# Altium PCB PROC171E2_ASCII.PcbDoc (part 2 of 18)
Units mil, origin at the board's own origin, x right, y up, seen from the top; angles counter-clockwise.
Board outline 7700 x 2300 mil, 6 copper layers (Top Layer, GND 1, SIG 1, SIG 2, GND 2, Bottom Layer), stack 61.062 mil thick; 938 components, 688 nets, 11933 pads, 1723 vias.
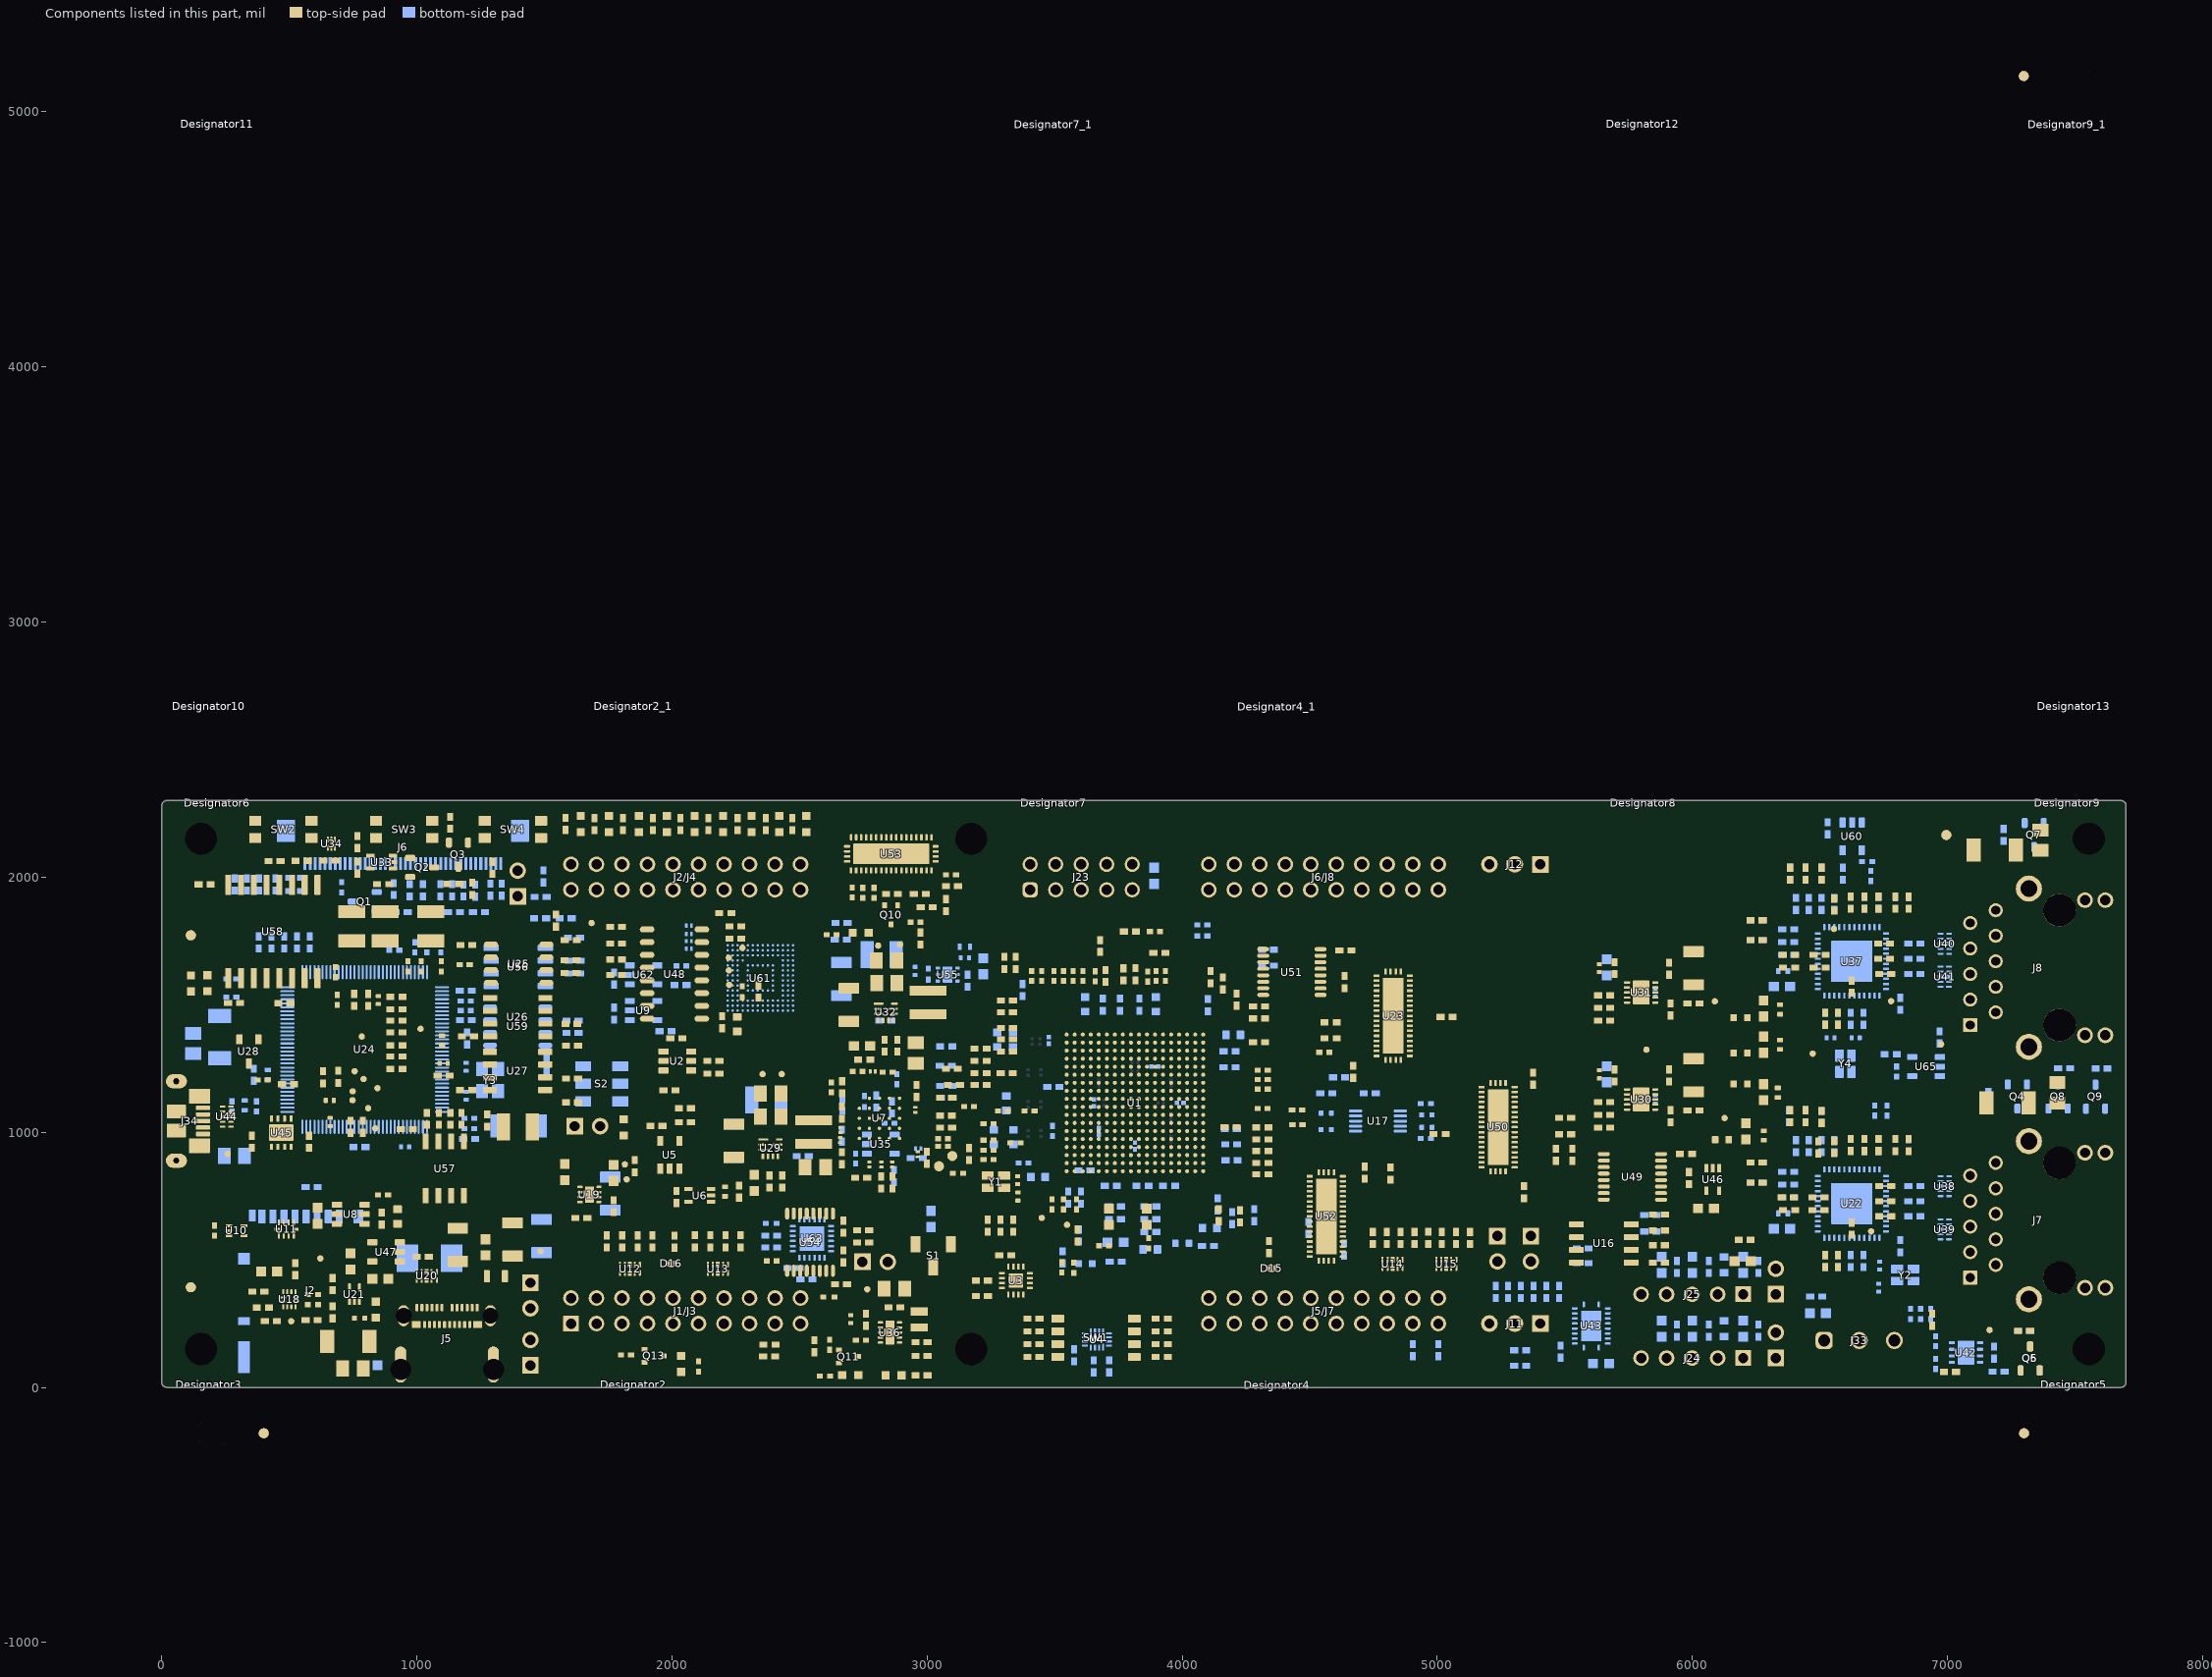
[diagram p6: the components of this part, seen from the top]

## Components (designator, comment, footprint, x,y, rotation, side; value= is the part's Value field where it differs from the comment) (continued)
C108 "GRM188R72A104KA35D" 0603 1771.58,840.73 r90 top
C109 "GRM1555C1H102JA01D" 0402 1771.58,710 r270 top
C110 "GRM188R72A104KA35D" 0603 740,493.54 r90 top
C111 "GRM155R71E104KE14D" 0402 5009,992.82 r0 top
C112 "GJM1555C1H120JB01D" FP-GJM1555C1H120JB01D_0402-MFG 6730.7,390.77 r270 bottom
C113 "GJM1555C1H120JB01D" FP-GJM1555C1H120JB01D_0402-MFG 6733.44,477.16 r270 bottom
C114 "GRM188Z71A106MA73D" 0603 6279,1343.28 r90 top
C115 "GRM1555C1E103JE01D" FP-GRM1555C1E103JE01D_0402-MFG 6344,1343.46 r270 top
C116 "GRM155R70J105MA12D" 0402 6556.28,941.71 r90 top
C117 "GRM155R71E104KE14D" 0402 6556.28,945.08 r90 bottom
C118 "GRM155R70J105MA12D" 0402 6493.94,745.04 r0 top
C119 "GRM155R71E104KE14D" 0402 6374.14,745.04 r180 top
C120 "GRM155R70J105MA12D" 0402 6755.41,729.88 r180 top
C121 "GRM155R71E104KE14D" 0402 6870.21,729.88 r0 bottom
C122 "GRM188Z71A106MA73D" 0603 6210,1003.65 r90 top
C123 "GRM1555C1E103JE01D" FP-GRM1555C1E103JE01D_0402-MFG 6280.09,987.15 r270 top
C124 "GRM155R70J105MA12D" 0402 6755.41,670.83 r180 top
C125 "GRM155R71E104KE14D" 0402 6870.21,670.83 r0 bottom
C126 "GRM155R70J105MA12D" 0402 6755.41,788.94 r180 top
C127 "GRM155R71E104KE14D" 0402 6870.21,788.94 r0 bottom
C128 "GRM188Z71A106MA73D" 0603 6351.36,621.24 r180 bottom
C129 "GRM1555C1E103JE01D" FP-GRM1555C1E103JE01D_0402-MFG 6355.51,681.97 r0 bottom
C130 "GRM155R70J105MA12D" 0402 6625,622.13 r90 top
C131 "GRM155R71E104KE14D" 0402 6670,495 r270 bottom
C132 "GRM155R70J105MA12D" 0402 6493.94,695.04 r0 top
C133 "GRM155R71E104KE14D" 0402 6379.14,695.04 r180 top
C134 "GRM155R71E104KE14D" 0402 1205.5,974.22 r180 bottom
C135 "GRM1555C1E103JE01D" FP-GRM1555C1E103JE01D_0402-MFG 325,1105.38 r90 bottom
C136 "GRM155R71E104KE14D" 0402 1607.87,1117.23 r180 top
C137 "GRM155R71E104KE14D" 0402 1607.87,1340 r180 top
C138 "GRM155R71E104KE14D" 0402 1603.77,1753.19 r180 top
C139 "GRM155R71E104KE14D" 0402 1193.04,1165.27 r0 top
C140 "GRM155R71E104KE14D" 0402 1200.59,1376.28 r0 top
C141 "GRM155R71E104KE14D" 0402 1194.14,1733.64 r0 top
C142 "GRM155R71E104KE14D" 0402 1191.36,1554.93 r0 bottom
C143 "GJM1555C1H8R0DB01D" FP-GJM1555C1H8R0DB01D_0402-MFG 1193.21,1143.27 r270 bottom
C144 "GJM1555C1H8R0DB01D" FP-GJM1555C1H8R0DB01D_0402-MFG 1193.07,1256.29 r90 bottom
C145 "GRM155R71E104KE14D" 0402 495.31,1188.47 r0 top
C146 "GRM155C71A105KE11D" FP-GRM155C71A105KE11D_0402-MFG 954.01,942.22 r180 bottom
C147 "GRM155R71E104KE14D" 0402 787.63,1021.22 r90 top
C148 "GRM155C71A105KE11D" FP-GRM155C71A105KE11D_0402-MFG 848.81,1517.94 r270 top
C149 "GRM1555C1E103JE01D" FP-GRM1555C1E103JE01D_0402-MFG 1098.65,1359.8 r90 top
C150 "GRM155R71E104KE14D" 0402 480.5,1505.66 r0 top
C151 "GRM155R71E104KE14D" 0402 360.82,1225.67 r270 bottom
C152 "GRM1555C1E103JE01D" FP-GRM1555C1E103JE01D_0402-MFG 415.82,1225.67 r90 bottom
C153 "GRM155C81C225KE11D" 0402 1105,1221.57 r180 top
C154 "GRM155R71E104KE14D" 0402 774.98,941.85 r180 bottom
C155 "GRM155R71E104KE14D" 0402 740.38,1021.22 r270 top
C156 "GRM155C71A105KE11D" FP-GRM155C71A105KE11D_0402-MFG 1105,1270 r180 top
C157 "GRM21BZ71A226ME15L" 0805_HV 2387.33,1061.68 r180 top
C158 "GRM21BZ71A226ME15L" 0805_HV 2387.33,1151.68 r180 top
C159 "GRM32ER71A476ME15L" 1210_270 2370.42,1126.68 r180 bottom
C160 "GRM188R71E474KA12D" 0603 2322.84,801.68 r270 top
C161 "GRM188Z71C475KE21D" 0603 5664.06,1227.1 r90 bottom
C162 "GRM155C71A105KE11D" FP-GRM155C71A105KE11D_0402-MFG 5635.58,1227.04 r270 top
C163 "GRM155R71E104KE14D" 0402 5695.21,1222.1 r90 top
C164 "GRM32EC72A106KE05L" FP-GRM32EC72A106KE05L_1210-MFG 6004.13,1223.43 r270 top
C165 "GRM155R71E104KE14D" 0402 5909.13,1222.1 r90 top
C166 "GCM155R72A272KA37D" FP-GCM155R72A272KA37D_0402-MFG 5854.25,1128.43 r270 bottom
C167 "GRM32EC72A106KE05L" FP-GRM32EC72A106KE05L_1210-MFG 2242.33,966.68 r270 top
C168 "GRM32EC72A106KE05L" FP-GRM32EC72A106KE05L_1210-MFG 2242.33,966.68 r270 bottom
C169 "GRM21BZ71A226ME15L" 0805_HV 2842.02,1584.28 r180 top
C170 "GRM21BZ71A226ME15L" 0805_HV 2841.41,1673.07 r180 top
C171 "GRM32ER71A476ME15L" 1210_270 2821.87,1696.91 r180 bottom
C172 "GRM188Z71C475KE21D" 0603 5664.13,1646.29 r90 bottom
C173 "GRM155C71A105KE11D" FP-GRM155C71A105KE11D_0402-MFG 5635.58,1643.07 r270 top
C174 "GRM155R71E104KE14D" 0402 5695.21,1643.29 r90 top
C175 "GRM32EC72A106KE05L" FP-GRM32EC72A106KE05L_1210-MFG 6004.13,1642.62 r270 top
C176 "GRM155R71E104KE14D" 0402 5909.13,1641.29 r90 top
C177 "GRM188R71E474KA12D" 0603 2745.09,1338.05 r180 top
C178 "GCM155R72A272KA37D" FP-GCM155R72A272KA37D_0402-MFG 5854.25,1547.62 r270 bottom
C179 "GRM32EC72A106KE05L" FP-GRM32EC72A106KE05L_1210-MFG 2663.88,1600.34 r270 bottom
C180 "GRM32EC72A106KE05L" FP-GRM32EC72A106KE05L_1210-MFG 2694,1499.3 r270 top
C181 "GRM155R71E104KE14D" 0402 657.31,2065 r180 top
C182 "GRM155R71E104KE14D" 0402 766.92,2037.31 r90 top
C183 "GRM155R71E104KE14D" 0402 522.55,1944.88 r0 bottom
C184 "GRM155R71E104KE14D" 0402 522.55,1997.05 r0 bottom
C185 "GRM21BZ71A226ME15L" 0805_HV 2872,387 r180 top
C186 "GRM155R71E104KE14D" 0402 2872,314 r180 top
C187 "GRM155C71A105KE11D" FP-GRM155C71A105KE11D_0402-MFG 2700.34,267.42 r270 top
C188 "GRM155R71E104KE14D" 0402 2760.42,264.96 r90 top
C189 "GJM1555C1H120JB01D" FP-GJM1555C1H120JB01D_0402-MFG 6541.38,1370 r0 bottom
C190 "GJM1555C1H120JB01D" FP-GJM1555C1H120JB01D_0402-MFG 6640.35,1370.13 r180 bottom
C191 "GRM188Z71A106MA73D" 0603 6279,1485.21 r90 top
C192 "GRM1555C1E103JE01D" FP-GRM1555C1E103JE01D_0402-MFG 6344,1481.27 r270 top
C193 "GRM155R70J105MA12D" 0402 6556.28,1891.71 r90 top
C194 "GRM155R71E104KE14D" 0402 6556.28,1895.08 r90 bottom
C195 "GRM155R70J105MA12D" 0402 6498.94,1695.04 r0 top
C196 "GRM155R71E104KE14D" 0402 6379.14,1695.04 r180 top
C197 "GRM155R70J105MA12D" 0402 6751.41,1679.88 r180 top
C198 "GRM155R71E104KE14D" 0402 6870.21,1679.88 r0 bottom
C199 "GRM188Z71A106MA73D" 0603 6278.93,1156.97 r270 top
C200 "GRM1555C1E103JE01D" FP-GRM1555C1E103JE01D_0402-MFG 6334.77,1155 r90 top
C201 "GRM155R70J105MA12D" 0402 6755.41,1620.83 r180 top
C202 "GRM155R71E104KE14D" 0402 6870.21,1620.83 r0 bottom
C203 "GRM155R70J105MA12D" 0402 6751.41,1738.94 r180 top
C204 "GRM155R71E104KE14D" 0402 6870.21,1738.94 r0 bottom
C205 "GRM188Z71A106MA73D" 0603 6351.36,1571.24 r180 bottom
C206 "GRM1555C1E103JE01D" FP-GRM1555C1E103JE01D_0402-MFG 6355.51,1631.97 r0 bottom
C207 "GRM155R70J105MA12D" 0402 6625,1570.47 r90 top
C208 "GRM155R71E104KE14D" 0402 6670,1445 r270 bottom
C209 "GRM155R70J105MA12D" 0402 6498.94,1645.04 r0 top
C210 "GRM155R71E104KE14D" 0402 6379.14,1645.04 r180 top
C211 "GRM188R72A104KA35D" 0603 5880,230 r90 bottom
C212 "GRM188R72A104KA35D" 0603 5880,480 r90 bottom
C213 "GRM188R72A104KA35D" 0603 3890,2005 r270 bottom
C214 "GRM1885C1H102JA01D" 0603 6199.18,230 r90 bottom
C215 "GQM1875C2E101JB12D" FP-GQM1875C2E101JB12D_0603-MFG 6124.18,230 r270 bottom
C216 "GRM1885C1H102JA01D" 0603 6000,230 r90 bottom
C217 "GRM1885C1H102JA01D" 0603 6199.18,480 r90 bottom
C218 "GQM1875C2E101JB12D" FP-GQM1875C2E101JB12D_0603-MFG 6124.18,480 r270 bottom
C219 "GRM1885C1H102JA01D" 0603 6000,480 r90 bottom
C220 "GRM1885C1H102JA01D" 0603 6492.17,290.82 r0 bottom
C221 "GRM1885C1H102JA01D" 0603 6197.13,494.67 r180 top
C222 "GRM155R71H472KA01D" 0402 6940,265 r90 top
C223 "GRM155R71E104KE14D" 0402 5483.66,140.04 r90 bottom
C224 "GRM188R72A104KA35D" 0603 5642.05,93.47 r180 bottom
C225 "GRM155R71E104KE14D" 0402 7182.8,136.46 r270 bottom
C226 "GRM155R71E104KE14D" 0402 7010,60.4 r180 top
C227 "GRM21BZ71E106KE15L" 0805_HV 285,906.68 r0 bottom
C228 "GJM1555C1H150FB01D" FP-GJM1555C1H150FB01D_0402-MFG 658.65,1124.76 r0 top
C229 "GR442QR73D102KW01L" 1808 731.46,180.12 r0 top
C230 "GR442QR73D102KW01L" 1808 227.89,1373.06 r270 bottom
C231 "GRM155C81C225KE11D" 0402 352.83,962.27 r90 top
C232 "GRM155C71A105KE11D" FP-GRM155C71A105KE11D_0402-MFG 660,1040.15 r270 top
C233 "GRM155R71E104KE14D" 0402 577.56,962.27 r270 top
C234 "GR442QR73D102KW01L" 1808 1398.86,1025 r0 bottom
C235 "GR442QR73D102KW01L" 1808 7235,1115 r0 top
C236 "CL10A335KP8NNNC" FP-CL10A335KP8NNNC_0603-MFG 2255.95,1423.5 r270 top
C237 "GRM155R71E104KE14D" 0402 2195.94,1431.38 r270 top
C238 "GRM155R71E104KE14D" 0402 5376.11,1209.78 r270 top
C239 "GRM155R71E104KE14D" 0402 5339.88,764.77 r90 top
C240 "GRM155R71E104KE14D" 0402 4670.38,1236.85 r90 top
C241 "GRM155R71E104KE14D" 0402 4636.65,1588.39 r90 top
C242 "GRM155R71E104KE14D" 0402 5036.38,1451.95 r180 top
C243 "GRM155R71E104KE14D" 0402 4495.23,625.31 r90 bottom
C244 "GRM155R71E104KE14D" 0402 4635,540.45 r270 bottom
C245 "GRM155R71E104KE14D" 0402 4715,841.18 r270 top
C246 "GRM155R71E104KE14D" 0402 4640,1712.48 r180 top
C247 "GR442QR73D102KW01L" 1808 7185.15,2106.97 r0 top
C248 "GRM188R72A104KA35D" 0603 6053.19,701.15 r180 top
C249 "GRM188R72A104KA35D" 0603 856.86,425.41 r0 top
C250 "GRM155R71E104KE14D" 0402 283.47,1506.27 r0 top
C251 "GRM155R71E104KE14D" 0402 1197.04,1367.79 r90 bottom
C252 "GRM155R71E104KE14D" 0402 1508.47,1266.6 r270 bottom
C253 "GRM155R71H104KE14D" FP-GRM155R71H104KE14D_0402-MFG 2953.5,1632.38 r90 bottom
C254 "KGM05CR51A106MH" FP-KGM05CR51A106MH_0402-MFG 3004.7,1619.91 r270 bottom
C255 "GRM155R71H104KE14D" FP-GRM155R71H104KE14D_0402-MFG 3148.3,1684.38 r0 bottom
C256 "GRM155R61E225KE11D" 0402_070 3148.3,1727.09 r180 bottom
C257 "GRM155R71E104KE14D" 0402 3617.11,851 r180 bottom
C258 "KGM05CR51A106MH" FP-KGM05CR51A106MH_0402-MFG 2754.67,1120.32 r90 bottom
C259 "885012105010" 0402 2870.35,828.59 r270 bottom
C260 "885012105010" 0402 2662.59,404.5 r0 top
C261 "KGM05CR51A106MH" FP-KGM05CR51A106MH_0402-MFG 2615.34,354.8 r180 top
C262 "GRM155R71E104KE14D" 0402 168.23,1971.27 r180 top
C263 "885012105010" 0402 6589.21,2013.14 r270 bottom
C264 "885012105010" 0402 2338.77,1551.57 r270 top
C265 "KGM05CR51A106MH" FP-KGM05CR51A106MH_0402-MFG 2274.78,1550.65 r270 top
C266 "C1005X6S1C105K050BC" 0402 2664.95,1820.24 r0 bottom
C267 "885012105010" 0402 2033.53,1577 r0 bottom
C268 "885012105010" 0402 2389,548.03 r180 bottom
C269 "KGM05CR51A106MH" FP-KGM05CR51A106MH_0402-MFG 2389,642.68 r180 bottom
C270 "885012105010" 0402 6777.35,1305.89 r180 bottom
C271 "885012105010" 0402 2862.46,1097.32 r90 bottom
C272 "885012105010" 0402 2667.72,1107.14 r270 bottom
D1 "SMBJ6.5CA" SMB-Bi 1049.65,505.45 r0 bottom
D2 "150060VS75000" WL-SMCW_GREEN 1810.94,1018.81 r270 top
D3 "150060VS75000" WL-SMCW_GREEN 178.78,1584.03 r90 top
D4 "150060VS75000" WL-SMCW_GREEN 2526.43,2208.3 r90 top
D5 "150060VS75000" WL-SMCW_GREEN 2036.27,91.9 r270 top
D6 "150060VS75000" WL-SMCW_GREEN 2868.49,47.06 r0 top
D7 "150060VS75000" WL-SMCW_GREEN 2421.16,2208.3 r90 top
D8 "150060VS75000" WL-SMCW_GREEN 2312.35,2208.3 r90 top
D9 "150060VS75000" WL-SMCW_GREEN 2200.52,2208.3 r90 top
D10 "150060VS75000" WL-SMCW_GREEN 2088.59,2208.3 r90 top
D11 "150060VS75000" WL-SMCW_GREEN 1980.11,2208.3 r90 top
D12 "150060VS75000" WL-SMCW_GREEN 1870.7,2208.3 r90 top
D13 "150060VS75000" WL-SMCW_GREEN 1753.16,2208.3 r90 top
D14 "150060VS75000" WL-SMCW_GREEN 1642.17,2208.3 r90 top
D15 "TPD1E01B04DPYR" DPY0002A 4351.58,466.66 r180 top
D16 "TPD1E01B04DPYR" DPY0002A 1997.72,485.1 r180 top
Designator2 "Comment" BRAKE_WAY_HOLES1X3 1848.57,-39.37 r0 top
Designator2_1 "Comment" BRAKE_WAY_HOLES1X3 1848.57,2620.63 r0 top
Designator3 "Comment" BRAKE_WAY_HOLES1X3 184.09,-39.37 r0 top
Designator4 "Comment" BRAKE_WAY_HOLES1X3 4372.53,-40.63 r0 top
Designator4_1 "Comment" BRAKE_WAY_HOLES1X3 4372.53,2619.37 r0 top
Designator5 "Comment" BRAKE_WAY_HOLES1X3 7494.59,-39.37 r0 top
Designator6 "Comment" BRAKE_WAY_HOLES1X3 218.32,2340.63 r180 top
Designator7 "Comment" BRAKE_WAY_HOLES1X3 3496.1,2339.37 r180 top
Designator7_1 "Comment" BRAKE_WAY_HOLES1X3 3496.1,4999.37 r180 top
Designator8 "Comment" BRAKE_WAY_HOLES1X3 5807.39,2340.63 r180 top
Designator9 "Comment" BRAKE_WAY_HOLES1X3 7469.96,2339.37 r180 top
Designator9_1 "Comment" BRAKE_WAY_HOLES1X3 7469.96,4999.37 r180 top
Designator10 "Comment" BRAKE_WAY_HOLES1X3 184.09,2620.63 r0 top
Designator11 "Comment" BRAKE_WAY_HOLES1X3 217.32,5000.63 r180 top
Designator12 "Comment" BRAKE_WAY_HOLES1X3 5806.39,5000.63 r180 top
Designator13 "Comment" BRAKE_WAY_HOLES1X3 7494.59,2620.63 r0 top
DS1 "150060RS75000" WL-SMCW_RED 2739.41,1781.37 r180 top
DS2 "150060RS75000" WL-SMCW_RED 2698.87,47.97 r180 top
DS3 "150060RS75000" WL-SMCW_RED 115.08,1583.47 r90 top
DS4 "150060RS75000" WL-SMCW_RED 838.68,304.16 r270 top
FB1 "BLM18EG121SN1D" FP-BLM18EG121SN1D_0603-MFG 4000.08,564.71 r180 bottom
FB2 "BLM18EG121SN1D" FP-BLM18EG121SN1D_0603-MFG 3621.02,485 r180 bottom
FB3 "BLM18EG121SN1D" FP-BLM18EG121SN1D_0603-MFG 6188.68,1310.55 r0 top
FB4 "BLM18EG121SN1D" FP-BLM18EG121SN1D_0603-MFG 6115.92,970.9 r0 top
FB5 "BLM18EG121SN1D" FP-BLM18EG121SN1D_0603-MFG 6188.68,1449.44 r0 top
FB6 "BLM18EG121SN1D" FP-BLM18EG121SN1D_0603-MFG 6188.68,1188.64 r0 top
FID1 "Fiducial" Fiducial10-20 6995.38,2165 r90 top
FID2 "Fiducial" Fiducial10-20 113.79,392.07 r90 top
FID3 "Fiducial" Fiducial10-20 113.79,1771.83 r90 top
FID4 "Fiducial" Fiducial10-20 6995.38,2165 r90 bottom
FID5 "Fiducial" Fiducial10-20 113.79,392.07 r90 bottom
FID6 "Fiducial" Fiducial10-20 113.79,1771.83 r90 bottom
FID7 "Fiducial" Fiducial10-20 400,-180 r90 top
FID8 "Fiducial" Fiducial10-20 7300,-180 r270 top
FID9 "Fiducial" Fiducial10-20 7299,5140 r270 top
FID10 "Fiducial" Fiducial10-20 7299,5140 r90 bottom
FID11 "Fiducial" Fiducial10-20 7300,-180 r90 bottom
FID12 "Fiducial" Fiducial10-20 400,-180 r270 bottom
J1 "PBC02SAAN" Sullins_PBC02SAAN 1395.54,1975 r180 top locked
J1/J3 "SSQ-110-03-T-D" BoosterPack_40pin_J1J3 2054.17,300 r270 bottom locked
J2 "DM3BT-DSF-PEJS" Hirose_DM3BT-DSF-PEJS 570,362.52 r180 bottom locked
J2/J4 "SSQ-110-03-T-D" BoosterPack_40pin_J2J4 2054.17,2000 r270 bottom locked
J5 "2012670005" FP-2012670005_CONN_USB_9MM39_8MM21-MFG 1118.35,154.53 r0 top locked
J5/J7 "SSQ-110-03-T-D" BoosterPack_40pin_J5J7 4554.17,300 r270 bottom locked
J6 "FH12A-40S-0.5SH(55)" FP-FH12A-40S-0.5SH(55)_FFC40-MFG 945.63,2200 r180 bottom locked
J6/J8 "SSQ-110-03-T-D" BoosterPack_40pin_J6J8 4554.17,2000 r270 bottom locked
J7 "LPJG16314A4NL" FP-LPJG16314A4NL_CONN_RJ45-MFG 7444,655 r90 top locked
J8 "LPJG16314A4NL" FP-LPJG16314A4NL_CONN_RJ45-MFG 7444,1645 r90 top locked
J9 "PBC02SAAN" Sullins_PBC02SAAN 1445,136.05 r180 top
J10 "PBC02SAAN" Sullins_PBC02SAAN 1445,360 r0 top
J11 "PBC03SAAN" PBC03SAAN 5304.17,250 r180 top locked
J12 "PBC03SAAN" PBC03SAAN 5304.17,2050 r180 top locked
J13 "PBC02SAAN" Sullins_PBC02SAAN 5235.83,543.25 r0 top
J14 "PBC02SAAN" Sullins_PBC02SAAN 5367.11,543.25 r0 top
J15 "PBC02SAAN" Sullins_PBC02SAAN 6327.06,165 r180 top
J16 "PBC02SAAN" Sullins_PBC02SAAN 6327.06,415 r180 top
J17 "PBC02SAAN" Sullins_PBC02SAAN 1668.62,1023.77 r90 top
J18 "PBC02SAAN" Sullins_PBC02SAAN 2796.34,491.93 r90 top
J23 "PRPC005DAAN-RC" Sullins_xxPC005DAAN-RC 3604.17,2000 r90 top locked
J24 "PEC05SAAN" Sullins_PxC05SAAN 5999.18,115 r180 top locked
J25 "PEC05SAAN" Sullins_PxC05SAAN 5999.18,365 r180 top locked
J33 "OSTTE030161" On-Shore_OSTTE030161 6654.17,183.86 r0 top locked
J34 "1051640001" Molex_1051640001 0,1044.08 r270 top
L1 "BLM21PG300SN1D" FP-BLM21PG300SN1D_0805-MFG 1309.67,435.62 r0 top
L2 "74438356022" WE-MAPI_4020 2555.75,1000.74 r90 top
L3 "74438356022" WE-MAPI_4020 3003.77,1508.9 r90 top
L4 "74405020100" FP-74405020100_SMT_IND_2MM0_1MM6-MFG 2968.49,266.14 r90 top
LBL1 "THT-14-423-10" Label_650x200 6610,2187.06 r0 top
Logo1 "CE Mark" CE_Mark_5mm 564.56,1375.69 r0 top
Logo2 "Texas Instruments" TI_Stacked_Overlay_Small 5135,1778.31 r0 top locked
Logo3 "FCC disclaimer" FCC_disclaimer 9836.36,4289 r270 bottom
Logo4 "WEEE logo" WEEE_Minimum 6005,838.02 r180 bottom
Q1 "IRLML6401TRPBF" SOT-23 795.63,1904.12 r180 bottom
Q2 "IRLML6401TRPBF" SOT-23 1021,2038 r0 top
Q3 "IRLML6401TRPBF" SOT-23 1163.12,2088.08 r270 top
Q4 "BSS123" SOT-23 7274.1,1140 r270 bottom
Q5 "BSS123" SOT-23 7324,113.66 r90 top
Q6 "BSS123" SOT-23 7324,113.66 r90 bottom
Q7 "BSS123" SOT-23 7340,2165 r270 bottom
Q8 "BSS123" SOT-23 7433.87,1140.67 r90 bottom
Q9 "BSS123" SOT-23 7580.33,1139.39 r90 bottom
Q10 "BSS223PWH6327" SOT-323 2859.06,1852.03 r270 top
Q11 "BSS123W-7-F" SOT-323 2692.53,120.9 r0 top
Q13 "BSS123W-7-F" SOT-323 1930,123.39 r0 top
R1 "ERJ-2RKF1002X" 0402 3237.47,633.24 r270 top
R2 "CRCW04022K67FKED" 0402 3337.66,633.24 r90 top
R3 "ERJ-2GE0R00X" 0402L 3575.19,468.53 r90 top
R4 "ERJ-2GE0R00X" 0402L 3240.9,969.06 r180 top
R5 "ERJ-2GE0R00X" 0402 1773.66,1464.57 r270 bottom
R6 "ERJ-2RKF1002X" 0402 2162.72,1229.13 r180 top
R7 "ERJ-2GE0R00X" 0402L 3410,1612.48 r270 top
R8 "ERJ-2RKF1002X" 0402 3576.64,125.28 r90 bottom
R9 "CRCW040222R0JNED" 0402 3097.27,1248.26 r0 top
R10 "ERJ-2RKF1002X" 0402 3215,358.58 r0 top
R11 "ERJ-2RKF1002X" 0402 3306.84,517.07 r0 top
R12 "CRCW040222R0JNED" 0402 3074.77,1135.05 r0 top
R13 "CRCW040222R0JNED" 0402 3105.15,1185.36 r0 top
R14 "ERJ-2RKF1002X" 0402 3417.2,119.51 r0 top
R15 "ERJ-2RKF1002X" 0402 3417.2,169.51 r0 top
R16 "ERJ-2RKF1002X" 0402 3417.2,219.51 r0 top
R17 "ERJ-2RKF1002X" 0402 3417.2,269.43 r0 top
R18 "ERJ-2GE0R00X" 0402 2050.8,1039.07 r0 top
R19 "ERJ-2RKF49R9X" 0402 2262.84,767.39 r270 top
R20 "ERJ-2RKF1002X" 0402 2050.8,1094.07 r180 top
R21 "ERJ-2GEJ102X" 0402 1545,1829.63 r90 top
R22 "ERJ-2GEJ102X" 0402 3920,119.51 r180 top
R23 "ERJ-2GEJ102X" 0402 3920,169.51 r180 top
R24 "ERJ-2GEJ102X" 0402 3920,219.51 r180 top
R25 "ERJ-2GEJ102X" 0402 3920,269.51 r180 top
R26 "ERJ-2GE0R00X" 0402L 2624.76,1175.79 r90 top
R27 "CRCW020122R0FNED" "FP-CRCW020122R0FNED_0201 (0603 metric)-MFG" 2820.72,873.38 r90 top
R28 "CRCW020122R0FNED" "FP-CRCW020122R0FNED_0201 (0603 metric)-MFG" 2660.72,1008.32 r270 top
R29 "CRCW020122R0FNED" "FP-CRCW020122R0FNED_0201 (0603 metric)-MFG" 2954.22,1087.86 r270 top
R30 "CRCW020122R0FNED" "FP-CRCW020122R0FNED_0201 (0603 metric)-MFG" 2965.47,935.56 r180 bottom
R31 "CRCW040210K0FKED" 0402L 3240.9,893.53 r0 top
R32 "ERJ-6GEY0R00V" 0805_HV 749.55,73.93 r180 top
R33 "ERJ-2GE0R00X" 0402L 3659.54,1611.36 r90 top
R34 "ERJ-2GE0R00X" 0402L 3573,1612.48 r90 top
R35 "ERJ-2GE0R00X" 0402L 3611,1612.48 r90 top
R36 "ERJ-2GE0R00X" 0402L 3535,1612.48 r90 top
R37 "ERJ-2GE0R00X" 0402L 3497,1612.48 r90 top
R38 "ERJ-2GE0R00X" 0402L 3449,1612.48 r90 top
R39 "CRCW040210K0FKED" 0402L 867.24,754.8 r180 top
R40 "CRCW040210K0FKED" 0402L 206.73,614.21 r90 top
R41 "CRCW040210K0FKED" 0402L 3678.01,1730 r90 bottom
R42 "ERJ-2RKF1002X" 0402 3164.53,914.8 r270 top
R43 "ERJ-2RKF1002X" 0402 2665.66,987 r270 bottom
R44 "ERJ-2GE0R00X" 0402L 3869.54,564.73 r90 top
R45 "ERJ-2GE0R00X" 0402L 3528.72,469.92 r90 top
R46 "CRCW040222R0JNED" 0402 3347.99,1663.62 r270 top
R47 "CRCW040222R0JNED" 0402 3303.11,1663.55 r270 top
R48 "CRCW040222R0JNED" 0402 3373.91,1557.47 r270 bottom
R49 "CRCW040222R0JNED" 0402 3312.84,1409.18 r0 top
R50 "CRCW040222R0JNED" 0402 3312.84,1516.7 r0 top
R51 "CRCW040222R0JNED" 0402 3312.84,1469.53 r0 top
R52 "CRCW040222R0JNED" 0402 3313.3,1316.91 r0 top
R53 "CRCW040222R0JNED" 0402 3075,1336.34 r0 bottom
R54 "CRCW040222R0JNED" 0402 3209.68,1327.26 r0 top
R55 "CRCW04024K70JNED" 0402 2382.33,167.34 r180 top
R56 "CRCW04024K70JNED" 0402 2380.96,121 r180 top
R57 "CRCW040222R0JNED" 0402 3209.68,1279.26 r0 top
R58 "CRCW040222R0JNED" 0402 3209.68,1231.26 r0 top
R59 "CRCW040222R0JNED" 0402 3075,1181.51 r0 bottom
R60 "CRCW040222R0JNED" 0402 3077.77,1135.05 r0 bottom
R61 "ERJ-2RKF33R0X" 0402L 4955.28,975.79 r0 bottom
R62 "ERJ-2RKF33R0X" 0402L 4955.28,1111.7 r0 bottom
R63 "ERJ-2GEJ152X" FP-ERJ-2GEJ152X_0402-MFG 4959.21,1019.06 r0 bottom
R64 "ERJ-2GEJ152X" FP-ERJ-2GEJ152X_0402-MFG 4959.21,1068.43 r0 bottom
R65 "CRCW040222R0JNED" 0402 4314.45,834.48 r180 top
R66 "CRCW040222R0JNED" 0402 4314.45,878.82 r180 top
R67 "CRCW040222R0JNED" 0402 4314.45,926.55 r180 top
R68 "CRCW040222R0JNED" 0402 4314.45,972.1 r180 top
R69 "CRCW040222R0JNED" 0402 4189.92,1020.57 r180 top
R70 "CRCW040222R0JNED" 0402 4314.45,1019.06 r180 top
R71 "ERJ-2RKF33R0X" 0402L 4315.34,1092.85 r180 top
R72 "ERJ-2RKF33R0X" 0402L 4451.61,1086.73 r180 top
R73 "ERJ-2GEJ152X" FP-ERJ-2GEJ152X_0402-MFG 4564.79,1010.55 r180 bottom
R74 "ERJ-2GEJ152X" FP-ERJ-2GEJ152X_0402-MFG 4564.79,1074.9 r180 bottom
R75 "ERJ-2GE0R00X" 0402L 4451.61,1029.87 r180 bottom
R76 "ERJ-2GE0R00X" 0402L 4452.24,1029.87 r180 top
R77 "ERJ-2GE0R00X" 0402L 4315.93,1205.86 r180 top
R78 "ERJ-2GE0R00X" 0402L 4557.16,1313.21 r180 top
R79 "ERJ-2GE0R00X" 0402L 4449.67,1086.88 r180 bottom
R80 "ERJ-2GE0R00X" 0402L 4315.93,1168.86 r180 top
R81 "CRCW040222R0JNED" 0402 4301.24,1492.68 r180 top
R82 "CRCW040222R0JNED" 0402 4212.87,1519.61 r270 top
R83 "CRCW040222R0JNED" 0402 4301.24,1353.13 r180 top
R84 "CRCW040222R0JNED" 0402 4301.24,1445.88 r180 top
R85 "CRCW040222R0JNED" 0402 4159.49,1583.39 r270 top
R86 "CRCW040222R0JNED" 0402 4110.9,1607.92 r270 top
R87 "ERJ-2GE0R00X" 0402L 4078.97,1769.24 r180 bottom
R88 "ERJ-2GE0R00X" 0402L 4078.97,1812.24 r180 bottom
R89 "ERJ-2GE0R00X" 0402L 592.82,324.31 r0 top
R90 "ERJ-2GE0R00X" 0402L 592.82,364.41 r0 top
R91 "CRCW0402200KJNED" 0402 587.51,263.69 r0 top
R92 "ERJ-2RKF1002X" 0402 669.95,404.69 r270 top
R93 "ERJ-2RKF1002X" 0402 669.95,294.31 r90 top
R94 "CRCW0402909KFKED" 0402 427.85,260.08 r180 top
R95 "CRCW04024K70JNED" 0402 396.4,312.6 r0 top
R96 "ERJ-2GEJ102X" 0402 5986.5,820 r270 top
R97 "ERJ-2GEJ102X" 0402 523.29,463.41 r270 top
R98 "ERJ-2RKF1002X" 0402 1645,663.27 r0 top
R99 "CRCW040222R0JNED" 0402 3074.04,1064.94 r0 top
R100 "ERJ-2GE0R00X" 0402 6375.51,745.04 r0 bottom
R101 "ERJ-2GE0R00X" 0402 6506.28,945 r270 bottom
R102 "ERJ-2GE0R00X" 0402 6375.51,795.04 r0 bottom
R103 "ERJ-2GE0R00X" 0402 6375.51,845.04 r0 bottom
R104 "ERJ-2GE0R00X" 0402 6406.28,945 r270 bottom
R105 "ERJ-2GE0R00X" 0402 6456.28,945 r270 bottom
R106 "ERJ-2GE0R00X" 0402 6493.31,940.44 r90 top
R107 "ERJ-2RKF1152X" 0402 6815,553.37 r90 bottom
R108 "CRCW04022K49FKED" 0402 6251.3,802.65 r180 top
R109 "CRCW04022K49FKED" 0402 6251.38,880.96 r180 top
R110 "CRCW04022K49FKED" 0402 6729.39,950.08 r90 top
R111 "CRCW04022K49FKED" 0402 6796.28,949.68 r90 top
R112 "CRCW04022K49FKED" 0402 6674.39,950.08 r90 top
R113 "CRCW04022K49FKED" 0402 6506.28,1059.68 r90 top
R114 "CRCW04022K49FKED" 0402 6520,495 r270 top
R115 "CRCW04022K49FKED" 0402 6383.01,1062.96 r90 top
R116 "CRCW04022K49FKED" 0402 6443.01,1062.97 r90 top
R117 "ERJ-2GE0R00X" 0402 6570,495 r90 bottom
R118 "ERJ-2GE0R00X" 0402 6520,495 r90 bottom
R119 "ERJ-2GE0R00X" 0402 6620,495 r90 bottom
R120 "CRCW04022K49FKED" 0402 6251.3,802.65 r0 bottom
R121 "CRCW04022K49FKED" 0402 6251.49,880.85 r0 bottom
R122 "CRCW04022K49FKED" 0402 6729.39,950.08 r270 bottom
R123 "CRCW04022K49FKED" 0402 6848,949.68 r270 top
R124 "CRCW04022K49FKED" 0402 6674.39,950.08 r270 bottom
R125 "CRCW04022K49FKED" 0402 6506.28,1059.68 r270 bottom
R126 "CRCW04022K49FKED" 0402 6570.85,495 r90 top
R127 "CRCW04022K49FKED" 0402 6379.14,1062.97 r270 bottom
R128 "CRCW04022K49FKED" 0402 6443.01,1062.97 r270 bottom
R129 "ERJ-2GE0R00X" 0402 380.5,1744.01 r270 bottom
R130 "ERJ-2GE0R00X" 0402L 1205.5,1054.21 r180 bottom
R131 "ERJ-2GE0R00X" 0402 430.5,1744.01 r270 bottom
R132 "ERJ-2GEJ101X" 0402L 1205.5,1014.22 r0 bottom
R133 "CRCW040233R2FKED" 0402 480.5,1744.01 r270 bottom
R134 "CRCW040233R2FKED" 0402 530.5,1744.01 r270 bottom
R135 "CRCW040233R2FKED" 0402 580.5,1744.01 r270 bottom
R136 "CRCW0402330KFKED" 0402L 275.17,1101.38 r90 bottom
R137 "CRCW0402330KFKED" 0402L 371.47,1101.38 r270 bottom
R138 "CRCW04021K00FKED" 0402L 1187.62,1656.39 r0 bottom
R139 "CRCW04021K00FKED" 0402L 1093.35,1724.68 r90 bottom
R140 "CRCW04021K00FKED" 0402L 1039.13,1724.68 r90 bottom
R141 "CRCW04021K00FKED" 0402L 992.24,1724.68 r90 bottom
R142 "CRCW040249R9FKED" 0402L 1191.36,1514.93 r0 bottom
R143 "CRCW040210K0FKED" 0402L 1191.36,1476.93 r0 bottom
R144 "CRCW04021K00FKED" 0402L 395.32,1204.12 r180 top
R145 "CRCW04024K87FKED" 0402L 911.79,1713.62 r0 bottom
R146 "ERJ-2RKF1002X" 0402 2512.33,906.68 r0 bottom
R147 "ERJ-2RKF1002X" 0402 5654.13,1117.63 r180 top
R148 "ERJ-6ENF1822V" 0805_HV 2562.66,862.92 r180 top
R149 "ERJ-2GE0R00X" 0402 5654.13,1017.63 r0 top
R150 "ERJ-2GE0R00X" 0402 5654.13,1067.63 r0 top
R151 "CRCW04023K57FKED" 0402 6004.13,1085.98 r0 top
R152 "CRCW04021K69FKED" 0402 5914.13,1062.36 r90 top
R153 "CRCW04022K49FKED" 0402 2432.33,806.68 r270 top
R154 "CRCW04024K99FKED" 0402 2382.33,806.68 r90 top
R155 "ERJ-2RKF1002X" 0402 5654.13,1536.82 r180 top
R156 "ERJ-2RKF1002X" 0402 2836.57,1437.88 r180 bottom
R157 "ERJ-2GE0R00X" 0402 5654.13,1436.82 r0 top
R158 "ERJ-2GE0R00X" 0402 5654.13,1486.82 r0 top
R159 "CRCW04021K87FKED" 0402 6004.13,1505.17 r0 top
R160 "ERJ-6ENF1822V" 0805_HV 2956.47,1310.85 r90 top
R161 "CRCW04024K99FKED" 0402 5914.13,1481.55 r90 top
R162 "CRCW040215K4FKED" 0402 2884,1339.3 r270 top
R163 "CRCW04024K99FKED" 0402 2834,1339.3 r90 top
R164 "CRCW040222R0JNED" 0402 3699.91,1612.61 r270 top
R165 "ERJ-2GE0R00X" 0402L 3491.78,1005.11 r90 bottom
R166 "CRCW040222R0JNED" 0402 3769.66,1618.82 r270 top
R167 "ERJ-2GE0R00X" 0402L 3240.9,1034.08 r0 top
R168 "ERJ-2GE0R00X" 0402L 3297.5,1083.59 r0 top
R169 "ERJ-2GE0R00X" 0402L 3935,1612.48 r270 top
R170 "ERJ-2GE0R00X" 0402L 3893.31,1786.65 r0 top
R171 "ERJ-2GE0R00X" 0402L 3897,1612.48 r270 top
R172 "ERJ-2GE0R00X" 0402L 3864.43,1609.98 r270 top
R173 "ERJ-2RKF1002X" 0402 3910.59,1702.62 r180 top
R174 "ERJ-2RKF1002X" 0402 3795.44,1786.65 r180 top
R175 "CRCW04024K70JNED" 0402 4904.17,146.03 r270 bottom
R176 "CRCW04024K70JNED" 0402 5004.17,146.03 r270 bottom
R177 "ERJ-2RKF1002X" 0402 909.28,1953.16 r270 bottom
R178 "ERJ-2RKF1002X" 0402 868,1973 r180 top
R179 "ERJ-2RKF1002X" 0402 766.92,2137.39 r90 top
R180 "ERJ-2GE0R00X" 0402L 706,1960 r90 bottom
R181 "ERJ-2RKF1002X" 0402 1130,2213 r90 top
R182 "ERJ-2RKF1002X" 0402 1228.48,1946.94 r270 bottom
R183 "ERJ-2RKF1002X" 0402 1616,1762 r180 bottom
R184 "ERJ-2RKF1002X" 0402 1216.66,1954.05 r270 top
R185 "ERJ-2RKF1002X" 0402 1243.82,1862.94 r180 bottom
R186 "ERJ-2RKF1002X" 0402 1145.21,1862.94 r180 bottom
R187 "ERJ-2RKF1002X" 0402 1049.67,1862.94 r180 bottom
R188 "ERJ-2RKF1002X" 0402 940.27,1862.94 r0 bottom
R189 "ERJ-2GE0R00X" 0402L 3586.2,717.13 r270 top
R190 "ERJ-2GE0R00X" 0402L 3535,717.13 r270 top
R191 "CRCW04024K70JNED" 0402 1483.38,1838.89 r180 bottom
R192 "CRCW04024K70JNED" 0402 1583.39,1838.79 r0 bottom
R193 "ERJ-2GE0R00X" 0402L 2740.82,184.29 r180 top
R194 "ERJ-2RKF1002X" 0402 2978.49,177.56 r0 top
R195 "ERJ-2RKF1003X" 0402 2978.49,122.56 r0 top
R196 "ERJ-2GE0R00X" 0402 6375.51,1695.04 r0 bottom
R197 "ERJ-2GE0R00X" 0402 6506.28,1895 r270 bottom
R198 "ERJ-2GE0R00X" 0402 6375.51,1745.04 r0 bottom
R199 "ERJ-2GE0R00X" 0402 6375.51,1795.04 r0 bottom
R200 "ERJ-2GE0R00X" 0402 6406.28,1895 r270 bottom
R201 "ERJ-2GE0R00X" 0402 6456.28,1895 r270 bottom
R202 "ERJ-2RKF1152X" 0402 6815,1503.37 r90 bottom
R203 "CRCW04022K49FKED" 0402 6251.38,1752.65 r180 top
R204 "CRCW04022K49FKED" 0402 6251.38,1830.96 r180 top
R205 "CRCW04022K49FKED" 0402 6506.28,2013.05 r90 top
R206 "CRCW04022K49FKED" 0402 6796.28,1899.68 r90 top
R207 "CRCW04022K49FKED" 0402 6674.39,1900.08 r90 top
R208 "CRCW04022K49FKED" 0402 6729.39,1900.08 r90 top
R209 "CRCW04022K49FKED" 0402 6520,1445 r270 top
R210 "CRCW04022K49FKED" 0402 6383.01,2012.97 r90 top
R211 "CRCW04022K49FKED" 0402 6443.01,2012.97 r90 top
R212 "ERJ-2GE0R00X" 0402 6570,1445 r90 bottom
R213 "ERJ-2GE0R00X" 0402 6520,1445 r90 bottom
R214 "ERJ-2GE0R00X" 0402 6620,1445 r90 bottom
R215 "CRCW04022K49FKED" 0402 6251.3,1752.65 r0 bottom
R216 "CRCW04022K49FKED" 0402 6251.38,1830.96 r0 bottom
R217 "CRCW04022K49FKED" 0402 6506.28,2013.05 r270 bottom
R218 "CRCW04022K49FKED" 0402 6848,1899.68 r270 top
R219 "CRCW04022K49FKED" 0402 6674.39,1900.08 r270 bottom
R220 "CRCW04022K49FKED" 0402 6729.39,1900.08 r270 bottom
R221 "CRCW04022K49FKED" 0402 6570.97,1444.88 r90 top
R222 "CRCW04022K49FKED" 0402 6383.01,2012.97 r270 bottom
R223 "CRCW04022K49FKED" 0402 6443.01,2012.97 r270 bottom
R224 "CRCW0402220RJNED" 0402 7160.2,1135 r270 bottom
R225 "ERJ-2GE0R00X" 0402L 6715,1084.62 r270 bottom
R226 "CRCW0402220RJNED" 0402 7300.38,221.46 r180 top
R227 "ERJ-2GE0R00X" 0402L 6762.73,1085 r270 bottom
R228 "CRCW0402220RJNED" 0402 7300.38,221.46 r180 bottom
R229 "ERJ-2GE0R00X" 0402L 6846.59,947.67 r270 bottom
R230 "CRCW0402220RJNED" 0402 7220,2165 r270 bottom
R231 "ERJ-2GE0R00X" 0402L 6700,2004.69 r270 bottom
R232 "CRCW0402220RJNED" 0402 7457.49,1251.28 r0 bottom
R233 "ERJ-2GE0R00X" 0402L 6795,1896.38 r270 bottom
R234 "CRCW0402220RJNED" 0402 7603.95,1250 r0 bottom
R235 "ERJ-2GE0R00X" 0402L 6848,1896.38 r270 bottom
R236 "ERJ-2RKF4992X" 0402 6259.18,222.12 r90 bottom
R237 "ERJ-2RKF4992X" 0402 6064.18,222.13 r90 bottom
R238 "ERJ-2RKF4992X" 0402 5940,222.13 r90 bottom
R239 "ERJ-2RKF4992X" 0402 6259.18,472.12 r90 bottom
R240 "ERJ-2RKF4992X" 0402 6064.18,472.13 r90 bottom
R241 "ERJ-2RKF4992X" 0402 5940,472.13 r90 bottom
R242 "ERJ-2RKF4992X" 0402 6485.13,355.53 r0 bottom
R243 "ERJ-2RKF4992X" 0402 6205,578.2 r180 top
R244 "CRCW040210K0FKED" 0402L 6935,287.55 r90 bottom
R245 "ERJ-2GE0R00X" 0402L 3377.95,879.39 r180 bottom
R246 "CRCW040261R9FKED" 0402L 6952.8,91.77 r90 bottom
R247 "CRCW040261R9FKED" 0402L 6952.8,181.14 r270 bottom
R248 "ERJ-2GE0R00X" 0402L 6855,287.55 r90 bottom
R249 "CRCW040222R0JNED" 0402 7200,61.46 r180 bottom
R250 "CRCW040210K0FKED" 0402L 6895,287.55 r270 bottom
R251 "CRCW040251K1FKED" 0402 631.97,1215.23 r90 top
R252 "CRCW040230K0FKED" 0402 691.97,1217.17 r270 top
R253 "ERJ-6GEY0R00V" 0805_HV 122.89,1348.06 r90 bottom
R254 "ERJ-6ENF1004V" 0805_HV 7430.57,1155 r90 top
R255 "ERJ-6ENF1004V" 0805_HV 7364,2145 r90 top
R256 "ERJ-2GEJ102X" 0402 4816.77,838.02 r90 top
R257 "ERJ-2RKF5100X" 0402 1853.71,866.9 r270 top
R258 "ERJ-2RKF1002X" 0402 2998.31,1881.79 r0 top
R259 "ERJ-2GEJ361X" 0402L 272.6,1530 r0 bottom
R260 "ERJ-2GEJ361X" 0402L 272.6,1601.11 r0 bottom
R261 "CRCW04021K00FKED" 0402L 965,1650 r270 top
R262 "ERJ-2RKF2200X" 0402 2367.5,2207.37 r270 top
R263 "ERJ-2RKF2200X" 0402 2257.41,2207.37 r270 top
R264 "ERJ-2RKF2200X" 0402 2142.37,2207.37 r270 top
R265 "ERJ-2GEJ361X" 0402L 2625.92,1774.32 r180 top
R266 "ERJ-2RKF2200X" 0402 2033.08,2207.37 r270 top
R267 "ERJ-2RKF2200X" 0402 1925,2207.37 r270 top
R268 "ERJ-2RKF1002X" 0402 2973.53,1759.53 r270 top
R269 "ERJ-2RKF1002X" 0402 2248.54,1807.28 r180 top
R270 "ERJ-2RKF1002X" 0402 1780.93,1676.88 r0 top
R271 "ERJ-2RKF1002X" 0402 1780.93,1804.54 r0 top
R272 "ERJ-2GEJ511X" 0402L 2955,1823.35 r180 top
R273 "ERJ-2RKF2200X" 0402 1807.38,2207.37 r270 top
R274 "ERJ-2RKF1002X" 0402 1780.93,1739.85 r0 top
R275 "ERJ-2RKF1002X" 0402 2248.54,1759.04 r180 top
R276 "ERJ-2RKF1002X" 0402 1780.93,1616.57 r0 top
R277 "ERJ-2RKF2200X" 0402 1696.59,2207.37 r270 top
R278 "ERJ-2GEJ102X" 0402 2209.15,1859.15 r180 top
R279 "ERJ-2RKF2200X" 0402 1583.17,2208.5 r270 top
R280 "CRCW040222R0JNED" 0402 3074.69,1018.53 r0 top
R281 "CRCW040222R0JNED" 0402 3073.87,1260.59 r0 bottom
R282 "CRCW040222R0JNED" 0402 4143,674.68 r90 top
R283 "CRCW040222R0JNED" 0402 4195.58,663.32 r90 bottom
R284 "CRCW040222R0JNED" 0402 4282.93,674.68 r90 bottom
R285 "CRCW040222R0JNED" 0402 4226.22,670 r90 top
R286 "ERJ-2GE0R00X" 0402L 4315.93,1243.37 r180 top
R287 "ERJ-2RKF1002X" 0402 5530,911.55 r90 top
R288 "ERJ-2RKF1002X" 0402 4581.73,1430.9 r0 top
R289 "ERJ-2GEJ102X" 0402 5465.31,911.55 r90 top
R290 "ERJ-2GEJ102X" 0402 4581.73,1367.93 r0 top
R291 "ERJ-2RKF1002X" 0402 4565,1152.36 r0 bottom
R292 "ERJ-2RKF1002X" 0402 5501.38,1057.02 r180 top
R293 "ERJ-2GEJ102X" 0402 4615.26,1215.33 r180 bottom
R294 "ERJ-2GEJ102X" 0402 5501.38,992.02 r180 top
R295 "ERJ-2RKF1002X" 0402 1990,1163.59 r0 top
R296 "ERJ-2RKF1002X" 0402 2017.48,1367.85 r180 top
R297 "CRCW040222R0JNED" 0402 3817.25,1619.25 r270 top
R298 "ERJ-2RKF1002X" 0402 4336.51,1715.49 r180 bottom
R299 "ERJ-2RKF1002X" 0402 1023.5,512.5 r0 top
R300 "ERJ-2GEJ102X" 0402 4336.51,1652.52 r180 bottom
R301 "ERJ-2RKF1002X" 0402 919.69,1437.81 r0 top
R302 "ERJ-2GEJ361X" 0402L 2599.61,45 r180 top
R303 "ERJ-2GEJ511X" 0402L 2617.63,167.05 r270 top
R304 "ERJ-2GEJ102X" 0402 2558.18,161.5 r90 top
R305 "ERJ-2RKF1002X" 0402 6620,950 r270 top
R306 "ERJ-2RKF1002X" 0402 6620,1900.08 r270 top
R307 "ERJ-2GE0R00X" 0402L 3693.94,555 r0 top
R308 "CRCW04021K00FKED" 0402L 1016.99,1650 r270 top
R309 "CRCW04021K00FKED" 0402L 1095.89,1650 r270 top
R310 "CRCW04021K00FKED" 0402L 1186.77,1656.39 r0 top
R311 "CRCW04021K00FKED" 0402L 681.33,1627.52 r270 top
R312 "CRCW04021K00FKED" 0402L 688.16,1518.99 r270 top
R313 "CRCW0402130RFKED" 0402 2471.37,2207.37 r270 top
R314 "ERJ-2GEJ361X" 0402L 2103.52,81.9 r90 top
R315 "CRCW0402130RFKED" 0402 2978.49,47.31 r0 top
R316 "ERJ-2RKF1002X" 0402 5570,545.04 r0 bottom
R317 "ERJ-2GEJ511X" 0402L 1819.99,127.49 r0 top
R318 "ERJ-2RKF1002X" 0402 5868.93,488.21 r180 top
R319 "ERJ-2RKF1002X" 0402 5835.31,675 r180 bottom
R320 "ERJ-2RKF1002X" 0402 5868.93,676.73 r180 top
R321 "ERJ-2RKF1002X" 0402 5868.93,556.99 r180 top
R322 "ERJ-2RKF1002X" 0402 5835.31,611.02 r180 bottom
R323 "ERJ-2RKF1002X" 0402 5868.93,615 r180 top
R324 "CRCW040233R2FKED" 0402 1602.32,1674.24 r180 top
R325 "CRCW040233R2FKED" 0402 1602.74,1624.01 r180 top
R326 "CRCW040233R2FKED" 0402 1605.89,1424.77 r180 top
R327 "CRCW040233R2FKED" 0402 1607.87,1210 r180 top
R328 "CRCW040233R2FKED" 0402 5325,85 r0 bottom
R329 "CRCW040233R2FKED" 0402 5325,145.09 r0 bottom
R330 "CRCW040233R2FKED" 0402 5229.44,373.51 r270 bottom
R331 "CRCW040233R2FKED" 0402 5277.45,373.51 r270 bottom
R332 "CRCW040233R2FKED" 0402 5327.45,373.51 r270 bottom
R333 "CRCW040233R2FKED" 0402 5377.45,373.51 r270 bottom
R334 "CRCW040233R2FKED" 0402 5428.06,373.51 r270 bottom
R335 "CRCW040233R2FKED" 0402 5478.01,373.51 r270 bottom
R336 "ERJ-2RKF1002X" 0402 919.69,1248.06 r0 top
R337 "ERJ-2RKF1002X" 0402 919.69,1340.53 r0 top
R338 "ERJ-2RKF1002X" 0402 919.69,1296.56 r0 top
R339 "ERJ-2RKF1002X" 0402 919.69,1530.84 r0 top
R340 "ERJ-2RKF1002X" 0402 919.69,1481.93 r0 top
R341 "ERJ-2RKF1002X" 0402 919.69,1390.96 r0 top
R342 "ERJ-2GE0R00X" 0402 287,1971 r90 bottom
R343 "ERJ-2GE0R00X" 0402 334.13,1971 r90 bottom
R344 "ERJ-2GE0R00X" 0402 381.31,1971.27 r90 bottom
R345 "ERJ-2GE0R00X" 0402 445,1971 r90 bottom
R346 "ERJ-2GE0R00X" 0402 971.74,1948.38 r90 bottom
R347 "ERJ-2GE0R00X" 0402 1024.02,1948.38 r90 bottom
R348 "ERJ-2GE0R00X" 0402 1092.26,1948.38 r90 bottom
R349 "ERJ-2GE0R00X" 0402 442.38,2063 r180 top
R350 "ERJ-2GE0R00X" 0402 1138.11,1948.38 r90 bottom
R351 "ERJ-2GE0R00X" 0402 1142.74,1973.49 r180 top
R352 "ERJ-2GE0R00X" 0402 1296,2036 r90 top
R353 "ERJ-2GE0R00X" 0402 548.38,2064 r180 top
R354 "ERJ-2GE0R00X" 0402 1182.29,1947.37 r90 bottom
R355 "ERJ-2GE0R00X" 0402 1288.1,1951.05 r90 bottom
R356 "ERJ-2GE0R00X" 0402 1331.93,1951.05 r90 bottom
R357 "ERJ-2GE0R00X" 0402 1496,2003 r90 bottom
R358 "ERJ-2GE0R00X" 0402 1485,1923 r180 bottom
R359 "ERJ-2GE0R00X" 0402 1610.28,1389.97 r0 bottom
R360 "ERJ-2GE0R00X" 0402L 3489.29,717.13 r270 top
R361 "CRCW020122R0FNED" "FP-CRCW020122R0FNED_0201 (0603 metric)-MFG" 2964.2,913.72 r270 top
R362 "RC0603FR-073K16L" 0603 3220.04,1650.81 r90 bottom
R363 "CRCW04021K50FKED" 0402 3159.18,1594.03 r90 bottom
R364 "ERJ-2RKF1002X" 0402 3019,1550.16 r0 bottom
R365 "CRCW020122R0FNED" "FP-CRCW020122R0FNED_0201 (0603 metric)-MFG" 2863.91,873.38 r90 top
R366 "CRCW020122R0FNED" "FP-CRCW020122R0FNED_0201 (0603 metric)-MFG" 2773.92,873.38 r90 top
R367 "ERJ-2RKF4992X" 0402 2666.59,898.31 r90 top
R368 "ERJ-2RKF4992X" 0402 2741.8,822.18 r0 top
R369 "ERJ-2RKF4992X" 0402 2863.91,802.7 r90 top
R370 "ERJ-2RKF4992X" 0402 2999.42,900.18 r90 top
R371 "ERJ-2RKF4992X" 0402 2959.45,898.17 r0 bottom
R372 "CRCW04024K70JNED" 0402 2959.2,1162.07 r90 top
R373 "ERJ-2RKF4992X" 0402 2666.41,1076.56 r270 top
R374 "ERJ-2RKF4992X" 0402 2820.1,802.7 r90 top
R375 "CRCW040210K0FKED" 0402L 2845.78,1236.03 r0 top
R376 "CRCW020122R0FNED" "FP-CRCW020122R0FNED_0201 (0603 metric)-MFG" 2659.78,969.17 r90 top
R377 "ERJ-2GE0R00X" 0402L 3240.9,929.6 r0 top
R378 "ERJ-2GE0R00X" 0402L 3346.47,958.84 r0 top
R379 "ERJ-2GE0R00X" 0402L 3401.94,1083.62 r0 top
R380 "ERJ-2GE0R00X" 0402L 3121.15,838.71 r0 top
R381 "CRCW020122R0FNED" "FP-CRCW020122R0FNED_0201 (0603 metric)-MFG" 2787.16,1238.43 r180 top
R382 "ERJ-2GE0R00X" 0402L 2727.95,1238.43 r0 top
R383 "CRCW040210K0FKED" 0402L 3093.74,2009.27 r0 top
R384 "CRCW040210K0FKED" 0402L 2792.16,1938.42 r270 top
R385 "CRCW040210K0FKED" 0402L 2748.06,1938.42 r270 top
R386 "CRCW040210K0FKED" 0402L 2706.97,1939.68 r270 top
R387 "CRCW040210K0FKED" 0402L 2719.82,896.93 r270 bottom
R388 "CRCW040210K0FKED" 0402L 2852.9,1034.74 r180 bottom
R389 "ERJ-2RKF1002X" 0402 3074.01,1890.2 r90 top
R390 "ERJ-2RKF1002X" 0402 2971.45,1933.65 r180 top
R391 "ERJ-2GEJ102X" 0402 3097.34,1964.83 r180 top
R392 "ERJ-2GEJ102X" 0402 2862.46,1934.22 r0 top
R393 "CRCW040222R0JNED" 0402 3210.21,1184.7 r0 top
R394 "ERJ-2GE0R00X" 0402L 2390.85,495.6 r0 top
R395 "ERJ-2RKF1002X" 0402 2749.31,615.17 r0 top
R396 "ERJ-2RKF1002X" 0402 2749.3,567.58 r0 top
R397 "ERJ-2GEJ102X" 0402 2671.47,629.92 r270 top
R398 "ERJ-2GEJ102X" 0402 2671.47,513.6 r90 top
R399 "CRCW04024K70JNED" 0402 754.13,1518.67 r270 top
R400 "CRCW04024K70JNED" 0402 809.19,1518.67 r270 top
R401 "CRCW040222R0JNED" 0402 3678.01,1730 r270 top
R402 "ERJ-2GE0R00X" 0402L 3164.64,1100.9 r0 top
R403 "ERJ-2GE0R00X" 0402L 3062.78,944.62 r0 top
R404 "ERJ-2GE0R00X" 0402L 3062.78,974.88 r0 top
R405 "ERJ-2GE0R00X" 0402 960.54,1011.75 r180 top
R406 "CRCW12100000Z0EAHP" 1210 1054.16,1807.58 r90 top
R407 "CRCW04024K70JNED" 0402 1131.33,1052.57 r90 top
R408 "CRCW04024K70JNED" 0402 1039.15,1052.57 r90 top
R409 "ERJ-2GE0R00X" 0402 1617.41,1622.73 r0 bottom
R410 "CRCW12100000Z0EAHP" 1210 875.14,1807.58 r90 top
R411 "ERJ-2GE0R00X" 0402 1617.87,1672.84 r0 bottom
R412 "CRCW12100000Z0EAHP" 1210 745.39,1807.58 r90 top
R413 "ERJ-2GE0R00X" 0402 1085.82,1052.57 r90 top
R414 "ERJ-2GE0R00X" 0402 1174.89,1052.57 r90 top
R415 "CRCW12100000Z0EAHP" 1210 1396.11,1021.01 r0 top
R416 "ERJ-2GE0R00X" 0402 1275.96,1046.03 r90 top
R417 "ERJ-2RKF1002X" 0402 6530.67,2191.29 r90 bottom
R418 "CRCW040210K0FKED" 0402L 6684.93,2060.88 r0 bottom
R419 "ERJ-2RKF1002X" 0402 2661.94,1755.01 r0 bottom
R420 "ERJ-2RKF1002X" 0402 1773.53,1602.86 r270 bottom
R421 "CRCW040210K0FKED" 0402L 2036.82,1652.21 r0 bottom
R422 "ERJ-2RKF1002X" 0402 2527.03,423.89 r0 bottom
R423 "ERJ-2RKF1002X" 0402 2476.41,468.17 r0 bottom
R424 "ERJ-2RKF1002X" 0402 6968.46,1371.69 r270 bottom
R425 "CRCW040210K0FKED" 0402L 6800.32,1237.87 r90 bottom
R426 "ERJ-2RKF1002X" 0402 2389,595.1 r180 bottom
R427 "ERJ-2GE0R00X" 0402 1192.08,1439.56 r180 bottom
R428 "ERJ-2GE0R00X" 0402 1610.28,1437.67 r180 bottom
R429 "CRCW020122R0FNED" "FP-CRCW020122R0FNED_0201 (0603 metric)-MFG" 2066.55,1776.94 r180 bottom
R430 "CRCW020122R0FNED" "FP-CRCW020122R0FNED_0201 (0603 metric)-MFG" 2066.55,1749.33 r180 bottom
R431 "CRCW020122R0FNED" "FP-CRCW020122R0FNED_0201 (0603 metric)-MFG" 2066.55,1719.72 r180 bottom
R432 "CRCW020122R0FNED" "FP-CRCW020122R0FNED_0201 (0603 metric)-MFG" 2066.55,1810.15 r180 bottom
R433 "CRCW040222R0JNED" 0402 3312.81,1364.34 r0 top
R434 "ERA-2APB621X" FP-ERA-2APB621X_0402-MFG 776.05,270.76 r180 top
R435 "CRCW040210K0FKED" 0402L 2881.36,1207.94 r90 bottom
R436 "CRCW040222R0JNED" 0402 3312.39,1231.67 r0 top
R437 "ERJ-2GEJ102X" 0402 2753.58,1284.43 r0 top
R438 "ERJ-2RKF1003X" 0402 2667.19,1176.34 r270 top
R439 "ERJ-2RKF1002X" 0402 378.9,374.61 r0 top
S1 "CAS-120TA" SW_CAS-120TA 3024.1,515.79 r270 top
S2 "CAS-D20TA" SW_CAS-D20TA 1724.71,1190 r180 bottom
SW1 "416131160804" FP-416131160804_SMT_SW-MFG 3662.3,194.51 r90 top
SW2 "434351045816" FP-434351045816_SMT_SW_4MM7_4MM5-MFG 477,2187 r180 top
SW3 "434351045816" FP-434351045816_SMT_SW_4MM7_4MM5-MFG 950,2187 r180 top
SW4 "434351045816" FP-434351045816_SMT_SW_4MM7_4MM5-MFG 1376.76,2187 r180 top
TP1 "TP_SM_1MM" TP_SM_1MM 3099.06,906.94 r90 top
TP2 "TP_SM_1MM" TP_SM_1MM 3046.89,866.63 r90 top
TP3 "TESTPOINT" TP_25MIL-SMT 621.55,505.45 r90 top
TP4 "TESTPOINT" TP_25MIL-SMT 1485,533.1 r180 top
TP5 "TESTPOINT" TP_25MIL-SMT 507.51,259.31 r90 top
TP6 "TESTPOINT" TP_25MIL-SMT 2765.45,384.45 r90 top
TP7 "TESTPOINT" TP_25MIL-SMT 6700.57,611.5 r180 top
TP8 "TESTPOINT" TP_25MIL-SMT 1822.57,815.29 r90 top
TP9 "TESTPOINT" TP_25MIL-SMT 2893.73,1735.51 r90 top
TP10 "TESTPOINT" TP_25MIL-SMT 2430,1228.07 r90 top
TP11 "TESTPOINT" TP_25MIL-SMT 6088.14,1513.04 r90 top
TP12 "TESTPOINT" TP_25MIL-SMT 6126.43,1055.82 r90 top
TP13 "TESTPOINT" TP_25MIL-SMT 1815.59,873.93 r90 top
TP14 "TESTPOINT" TP_25MIL-SMT 2808.54,1731.68 r90 top
TP15 "TESTPOINT" TP_25MIL-SMT 2355,1228.07 r90 top
TP16 "TESTPOINT" TP_25MIL-SMT 6471.65,1308.13 r90 top
TP17 "TESTPOINT" TP_25MIL-SMT 5820,1323.71 r90 top
TP18 "TESTPOINT" TP_25MIL-SMT 1685,1820 r90 top
TP19 "TESTPOINT" TP_25MIL-SMT 6779.03,1513.91 r0 top
TP20 "TESTPOINT" TP_25MIL-SMT 6555,1797.09 r270 top
TP21 "TESTPOINT" TP_25MIL-SMT 6975,1345.45 r90 top
TP22 "TESTPOINT" TP_25MIL-SMT 7165,225 r90 top
TP23 "TESTPOINT" TP_25MIL-SMT 258.56,915 r0 top
TP24 "TESTPOINT" TP_25MIL-SMT 748.48,1160.35 r0 top
TP25 "TESTPOINT" TP_25MIL-SMT 809.21,1094.23 r90 top
TP26 "TESTPOINT" TP_25MIL-SMT 756.03,1239.11 r0 top
TP27 "TESTPOINT" TP_25MIL-SMT 837.37,1015 r180 top
TP28 "TESTPOINT" TP_25MIL-SMT 791.17,1208.54 r270 top
TP29 "TESTPOINT" TP_25MIL-SMT 747.83,1125.66 r270 top
TP30 "TESTPOINT" TP_25MIL-SMT 845.57,1172.78 r270 top
TP31 "TESTPOINT" TP_25MIL-SMT 1014.53,1405.29 r90 top
TP32 "TESTPOINT" TP_25MIL-SMT 784.17,1375 r270 top
TP33 "TESTPOINT" TP_25MIL-SMT 3449.69,663.97 r90 top
TP34 "TESTPOINT" TP_25MIL-SMT 3548.66,637.21 r90 top
TP35 "TESTPOINT" TP_25MIL-SMT 2276.01,1722.81 r0 top
TP36 "TESTPOINT" TP_25MIL-SMT 2223.1,1683.84 r0 top
TP37 "TESTPOINT" TP_25MIL-SMT 2223.1,1634.27 r0 top
TP38 "TESTPOINT" TP_25MIL-SMT 2224.18,1577.6 r0 top
U1 "AM263PxC" ZCZ0324A-MFG 3814.85,1115.08 r0 top locked
U2 "SN74LVC1G11DBVR" DBV0006A_N 2021.24,1279.45 r0 top
U3 "TCA6408ARGTR" RGT0016A 3348.05,418.7 r90 top
U4 "SN74AVC4T245RSVR" RSV0016A 3666.07,187.78 r90 bottom
U5 "SN74LVC1G08DBVR" DBV0005A_N 1991.31,911.4 r90 top
U6 "SN74LVC1G17DCKR" DCK0005A_N 2108.67,752.39 r180 top
U7 "IS25LX256-LHLE" FP-IS25LX256-LHLE_TFBGA24-IPC_C 2813.29,1054.55 r0 top locked
U8 "TPS22918TDBVTQ1" DBV0006A_N 741.03,678.6 r180 top
U9 "SN74LVC1G08DBVR" DBV0005A_N 1888.61,1477.4 r0 bottom
U10 "TPD2E001DRLR" DRL0005A 292.78,614.21 r0 top
U11 "TPD6E001RSER" RSE0010A 488.2,620 r270 top
U12 "TPD4E02B04DQAR" DQA0010A#1 1835,464.48 r90 top
U13 "TPD4E02B04DQAR" DQA0010A#1 2180,465 r90 top
U14 "TPD4E02B04DQAR" DQA0010A#1 4825,484.12 r90 top
U15 "TPD4E02B04DQAR" DQA0010A#1 5035.4,484.26 r90 top
U16 "CAT24M01WI-GT3" SOIC-8 5652.8,564.14 r180 top
U17 "TS5A23159DGSR" DGS0010A_N 4767.68,1043.75 r0 bottom
U18 "TUSB320LIRWBR" RWB0012A 500.2,345.08 r0 top
U19 "TPS22965TDSGRQ1" DSG0008B 1676.92,755.91 r0 top
U20 "TPD4E02B04DQAR" DQA0010A#1 1038.54,436.99 r270 top
U21 "SN74AHC1G02DRLR" DRL0005A 755.3,365 r90 top
U22 "DP83869HMRGZT" RGZ0048B-MFG 6625.18,720.04 r180 bottom
U23 "TS3DDR3812RUAR" RUA0042A-MFG 4827.2,1456.5 r0 top
U24 "TM4C1294NCPDTT3" PDT0128A 795.5,1324.37 r0 bottom locked
U25 "ISO7220CDR" D0008B_N 1398.97,1660.47 r0 top
U26 "ISO7721DR" D0008B_HV 1395.62,1451.5 r180 top
U27 "ISO7721DR" D0008B_HV 1395,1240.27 r180 top
U28 "LM4040C25QDBZR" DBZ0003A_N 341.5,1316.65 r270 top
U29 "TPS62913RPUR" RPU0010A-MFG 2385.89,941.68 r180 top
U30 "TPS74801DRCR" DRC0010J 5799.13,1128.43 r0 top
U31 "TPS74801DRCR" DRC0010J 5799.13,1547.62 r0 top
U32 "TPS62913RPUR" RPU0010A-MFG 2837.56,1474.3 r180 top
U33 "SN74LVC1G07DCKT" DCK0005A_N 862,2059 r180 top
U34 "SN74LVC2G17DSF2" DSF0006A 665,2131.22 r270 top
U35 "SN74LVC1G08DBVR" DBV0005A_N 2818.52,953.35 r0 bottom
U36 "TPS62177DQCR" DQC0010A 2854.71,214.96 r0 top
U37 "DP83869HMRGZT" RGZ0048B-MFG 6625.18,1670.04 r180 bottom
U38 "TPD4E05U06DQAR" DQA0010A#2 6989.58,788.94 r180 bottom
U39 "TPD4E05U06DQAR" DQA0010A#2 6989.31,619.6 r180 bottom
U40 "TPD4E05U06DQAR" DQA0010A#2 6989.58,1738.94 r180 bottom
U41 "TPD4E05U06DQAR" DQA0010A#2 6989.31,1609.6 r180 bottom
U42 "TCAN1044VDRBTQ1" DRB0008J 7072.8,136.46 r180 bottom
U43 "TXB0108RGYR" RGY0020A 5603.66,240.62 r0 bottom
U44 "TPD4E02B04DQAR" DQA0010A#1 255,1060.81 r180 top
U45 "TPS79601DRBR" DRB0008B 468.69,998.32 r90 top
U46 "SN74LVC1G04DCKR" DCK0005A_N 6080,815 r270 top
U47 "SN74LVC1G08DBVR" DBV0005A_N 879.5,531 r180 top
U48 "TPIC2810D" D0016A_N 2010,1620 r180 top locked
U49 "SN74CB3Q3257PWR" PW0016A_L 5765,825.23 r0 top
U50 "TS3DDR3812RUAR" RUA0042A-MFG 5238.39,1020.04 r180 top
U51 "SN74CB3Q3257PWR" PW0016A_L 4430,1627.91 r0 top
U52 "TS3DDR3812RUAR" RUA0042A-MFG 4565,670 r180 top
U53 "TS3DDR3812RUAR" RUA0042A-MFG 2859.79,2091.04 r90 top locked
U54 "SN74CB3Q3257PWR" PW0016A_L 2541.2,569.21 r270 top
U55 "TLV75801PDRVR" DRV0006A 3080.26,1618 r180 bottom
U56 "ISO1641BDR" D0008A-MFG 1397.72,1648.36 r0 bottom
U57 "ISO1641BDR" D0008A-MFG 1109.51,857.47 r90 top
U58 "ISO6760DWR" DW0016A-MFG 435.25,1786.67 r90 top
U59 "ISO7220CDR" D0008B_N 1395.39,1415 r0 bottom
U60 "SN74LVC1G08DBVR" DBV0005A_N 6626.26,2159.77 r270 bottom
U61 "MTFC8GAMALBH-AAT" FP-MTFC8GAMALBH-AAT_TFBGA153-MFG 2346.33,1604.8 r270 bottom locked
U62 "SN74LVC1G08DBVR" DBV0005A_N 1888.61,1616.57 r0 bottom
U63 "TCA6416ARTWR" RTW0024B 2548.96,583.47 r270 bottom
U65 "SN74LVC1G08DBVR" DBV0005A_N 6915.81,1257.25 r180 bottom
Y1 "ABM10W-25.0000MHZ-4-D1X-T3" Abracon_ABM10W 3270,806.21 r90 top
Y2 "ABM10W-25.0000MHZ-4-D1X-T3" Abracon_ABM10W 6834.6,440.5 r90 bottom
Y3 "NX3225GA-16.000M-STD-CRG-1" NDK_NX3225GA 1287.13,1204.32 r180 bottom
Y4 "ABM10W-25.0000MHZ-4-D1X-T3" Abracon_ABM10W 6600,1268.41 r0 bottom
ZZ1 "This Assembly Note is for PCB labels only" AssemblyNoteLabel 139,3742 r0 top
ZZ2 "These assemblies are ESD sensitive, ESD precautions shall be observed." AssemblyNote 139,3642 r0 top
ZZ3 "These assemblies must be clean and free from flux and all contaminants. Use of no clean flux is not acceptable." AssemblyNote 139,3542 r0 top
ZZ4 "These assemblies must comply with workmanship standards IPC-A-610 Class 2, unless otherwise specified." AssemblyNote 139,3442 r0 top
? "Comment" MISTRAL_LOGO_25 6689.32,1155.04 r0 top
? "Comment" MHNP_M3_PANHEAD_PHILLIPS 3173.18,150 r0 top
? "Comment" MHNP_M3_PANHEAD_PHILLIPS 7554.17,150 r0 top
? "Comment" MHNP_M3_PANHEAD_PHILLIPS 7554.17,2150 r0 top locked
? "Comment" MHNP_M3_PANHEAD_PHILLIPS 3173.18,2150 r0 top locked
? "Comment" MHNP_M3_PANHEAD_PHILLIPS 154.17,2150 r0 top
? "Comment" MHNP_M3_PANHEAD_PHILLIPS 154.17,150 r0 top locked

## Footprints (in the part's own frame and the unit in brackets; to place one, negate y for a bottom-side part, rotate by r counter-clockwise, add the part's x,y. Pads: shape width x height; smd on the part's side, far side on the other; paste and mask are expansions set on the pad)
0201 [mm] "Data from Kemet datasheet CC101_COM dated 7/28/11"
  rect 0.46x0.42 smd mask+0: 1(-0.33,0) 2(0.33,0)
0402 [mm] "0402 from SM-752 data"
  rect 0.8x0.6 smd: 1(-0.6,0) 2(0.6,0)
  silkscreen extent -1.22,-0.52 1.22,0.52
0402_070 [mil] "SMD, 2-Leads, Body 1.2x0.7mm, Height 0.7mm"
  rect 15x24 smd: 1(-20,0) 2(20,0)
0402L [mm] "0402 from SM-752 data"
  rect 0.6x0.5 smd: 1(-0.5,0) 2(0.5,0)
0603 [mm] "0603 from SM-752 data"
  rect 1x0.95 smd: 1(-0.8,0) 2(0.8,0)
  silkscreen extent -1.52,-0.69 1.52,0.69
0805_HV [mil] "0805 with 30mil clearance between pads"
  rect 50x63 smd: 1(-40,0) 2(40,0)
  silkscreen extent -74,-40 74,40
1210 [mm] "1210 from SM-752 data"
  rect 1.3x2.7 smd: 1(-1.45,0) 2(1.45,0)
  silkscreen extent -2.32,-1.57 2.32,1.57
1210_270 [mm] "1210"
  rect 1.3x2.7 smd: 1(-1.45,0) 2(1.45,0)
  silkscreen extent -2.32,-1.57 2.32,1.57
1808 [mm] "Chip Capacitor, Body 4.6x2.0mm, IPC Medium Density"
  rect 1.4x2.3 smd: 1(-2.1,0) 2(2.1,0)
  silkscreen extent -3.1,-1.45 3.1,1.45
Abracon_ABM10W [mm] "SMD, 4-Leads, Body 2x2.5mm"
  rrect12% 0.85x1.2 smd: 1(-0.6,0.813) 2(-0.6,-0.813) 3(0.6,-0.813) 4(0.6,0.813)
AssemblyNote [mil] "Assembly Note"
AssemblyNoteLabel [mil] "Assembly Note for PCB Labels"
